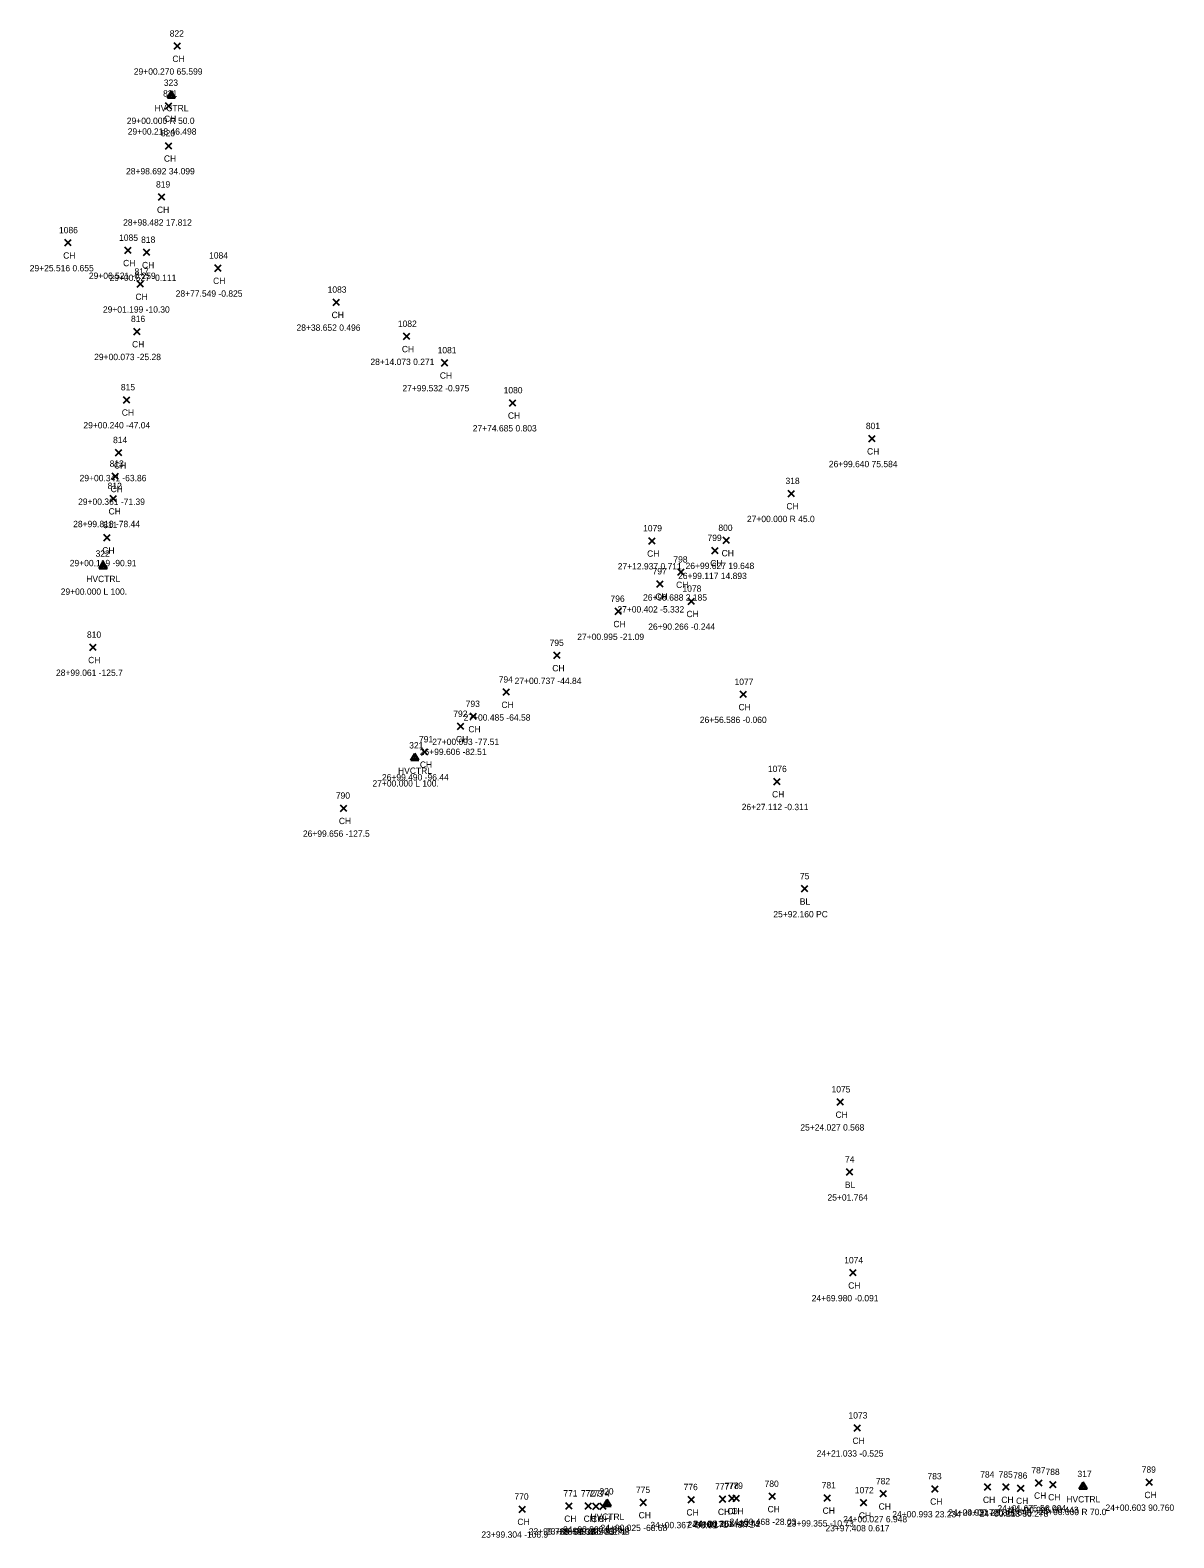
# Model space of a CAD drawing. Extents: x 89316 to 92454, y 84175 to 86051.
# Drawn here: x 90007.9 to 90368.2, y 85575.8 to 86051 of the extents above; entities that cross this region are included whole.
import ezdxf

# ---------------------------------------------------------------- set-up
doc = ezdxf.new("R2010")
doc.units = 0
for name, color, linetype in [('C_A', 7, 'Continuous'), ('C_C', 7, 'Continuous'), ('C_I', 7, 'Continuous'), ('C_TIC', 7, 'Continuous'), ('CPSM', 7, 'Continuous'), ('L_A', 7, 'Continuous'), ('L_C', 7, 'Continuous'), ('L_I', 7, 'Continuous'), ('L_TIC', 7, 'Continuous')]:
    doc.layers.add(name, color=color, linetype=linetype)

msp = doc.modelspace()

# ---------------------------------------------------------------- linework, layer by layer
at = {"layer": 'C_TIC'}
for points in [[(90250.87, 85779.38), (90252.87, 85781.38)], [(90252.87, 85779.38), (90250.87, 85781.38)], [(90265.06, 85690.1), (90267.06, 85692.1)], [(90267.06, 85690.1), (90265.06, 85692.1)]]:
    msp.add_lwpolyline(points, dxfattribs=at)
at = {"layer": 'CPSM'}
for p, q in [((90051.14, 86029.75), (90052.39, 86031.91)), ((90053.64, 86029.75), (90052.39, 86031.91)), ((90052.39, 86030.47), (90052.39, 86031.91)), ((90051.14, 86029.75), (90052.39, 86030.47)), ((90051.14, 86029.75), (90053.64, 86029.75)), ((90052.39, 86030.47), (90052.39, 86030.47)), ((90052.39, 86030.47), (90053.64, 86029.75)), ((90029.64, 85881.33), (90030.89, 85883.5)), ((90029.64, 85881.33), (90030.89, 85882.05)), ((90029.64, 85881.33), (90032.14, 85881.33)), ((90032.14, 85881.33), (90030.89, 85883.5)), ((90030.89, 85882.05), (90030.89, 85883.5)), ((90030.89, 85882.05), (90030.89, 85882.05)), ((90030.89, 85882.05), (90032.14, 85881.33)), ((90127.85, 85820.89), (90129.1, 85823.05)), ((90130.35, 85820.89), (90129.1, 85823.05)), ((90129.1, 85821.61), (90129.1, 85823.05)), ((90127.85, 85820.89), (90129.1, 85821.61)), ((90127.85, 85820.89), (90130.35, 85820.89)), ((90129.1, 85821.61), (90129.1, 85821.61)), ((90129.1, 85821.61), (90130.35, 85820.89)), ((90338.38, 85591.24), (90339.63, 85593.4)), ((90338.38, 85591.24), (90339.63, 85591.96)), ((90338.38, 85591.24), (90340.88, 85591.24)), ((90340.88, 85591.24), (90339.63, 85593.4)), ((90339.63, 85591.96), (90339.63, 85593.4)), ((90339.63, 85591.96), (90339.63, 85591.96)), ((90339.63, 85591.96), (90340.88, 85591.24)), ((90188.44, 85585.74), (90189.69, 85587.91)), ((90188.44, 85585.74), (90189.69, 85586.46)), ((90188.44, 85585.74), (90190.94, 85585.74)), ((90190.94, 85585.74), (90189.69, 85587.91)), ((90189.69, 85586.46), (90189.69, 85587.91)), ((90189.69, 85586.46), (90189.69, 85586.46)), ((90189.69, 85586.46), (90190.94, 85585.74))]:
    msp.add_line(p, q, dxfattribs=at)
at = {"layer": 'L_TIC'}
for points in [[(90053.23, 86045), (90055.23, 86047)], [(90055.23, 86045), (90053.23, 86047)], [(90050.59, 86026.09), (90052.59, 86028.09)], [(90052.59, 86026.09), (90050.59, 86028.09)], [(90050.55, 86013.56), (90052.55, 86015.56)], [(90052.55, 86013.56), (90050.55, 86015.56)], [(90048.36, 85997.42), (90050.36, 85999.42)], [(90050.36, 85997.42), (90048.36, 85999.42)], [(90018.83, 85983.01), (90020.83, 85985.01)], [(90020.83, 85983.01), (90018.83, 85985.01)], [(90037.71, 85980.62), (90039.71, 85982.62)], [(90039.71, 85980.62), (90037.71, 85982.62)], [(90043.66, 85979.99), (90045.66, 85981.99)], [(90045.66, 85979.99), (90043.66, 85981.99)], [(90066.05, 85975.01), (90068.05, 85977.01)], [(90068.05, 85975.01), (90066.05, 85977.01)], [(90041.59, 85969.99), (90043.59, 85971.99)], [(90043.59, 85969.99), (90041.59, 85971.99)], [(90103.39, 85964.26), (90105.39, 85966.26)], [(90105.39, 85964.26), (90103.39, 85966.26)], [(90040.53, 85955.02), (90042.53, 85957.02)], [(90042.53, 85955.02), (90040.53, 85957.02)], [(90125.52, 85953.5), (90127.52, 85955.5)], [(90127.52, 85953.5), (90125.52, 85955.5)], [(90137.48, 85945.17), (90139.48, 85947.17)], [(90139.48, 85945.17), (90137.48, 85947.17)], [(90037.29, 85933.5), (90039.29, 85935.5)], [(90039.29, 85933.5), (90037.29, 85935.5)], [(90158.93, 85932.54), (90160.93, 85934.54)], [(90160.93, 85932.54), (90158.93, 85934.54)], [(90272.06, 85921.27), (90274.06, 85923.27)], [(90274.06, 85921.27), (90272.06, 85923.27)], [(90034.83, 85916.85), (90036.83, 85918.85)], [(90036.83, 85916.85), (90034.83, 85918.85)], [(90033.75, 85909.4), (90035.75, 85911.4)], [(90035.75, 85909.4), (90033.75, 85911.4)], [(90033.12, 85902.37), (90035.12, 85904.37)], [(90035.12, 85902.37), (90033.12, 85904.37)], [(90246.66, 85903.96), (90248.66, 85905.96)], [(90248.66, 85903.96), (90246.66, 85905.96)], [(90031.14, 85890.06), (90033.14, 85892.06)], [(90033.14, 85890.06), (90031.14, 85892.06)], [(90202.78, 85889.04), (90204.78, 85891.04)], [(90204.78, 85889.04), (90202.78, 85891.04)], [(90226.25, 85889.18), (90228.25, 85891.18)], [(90228.25, 85889.18), (90226.25, 85891.18)], [(90222.66, 85886.01), (90224.66, 85888.01)], [(90224.66, 85886.01), (90222.66, 85888.01)], [(90211.91, 85879.21), (90213.91, 85881.21)], [(90213.91, 85879.21), (90211.91, 85881.21)], [(90205.35, 85875.47), (90207.35, 85877.47)], [(90207.35, 85875.47), (90205.35, 85877.47)], [(90215.17, 85870.01), (90217.17, 85872.01)], [(90217.17, 85870.01), (90215.17, 85872.01)], [(90192.15, 85866.83), (90194.15, 85868.83)], [(90194.15, 85866.83), (90192.15, 85868.83)], [(90026.69, 85855.49), (90028.69, 85857.49)], [(90028.69, 85855.49), (90026.69, 85857.49)], [(90172.9, 85852.93), (90174.9, 85854.93)], [(90174.9, 85852.93), (90172.9, 85854.93)], [(90156.88, 85841.38), (90158.88, 85843.38)], [(90158.88, 85841.38), (90156.88, 85843.38)], [(90231.57, 85840.65), (90233.57, 85842.65)], [(90233.57, 85840.65), (90231.57, 85842.65)], [(90142.57, 85830.57), (90144.57, 85832.57)], [(90144.57, 85830.57), (90142.57, 85832.57)], [(90146.47, 85833.71), (90148.47, 85835.71)], [(90148.47, 85833.71), (90146.47, 85835.71)], [(90131.2, 85822.52), (90133.2, 85824.52)], [(90133.2, 85822.52), (90131.2, 85824.52)], [(90242.13, 85813.17), (90244.13, 85815.17)], [(90244.13, 85813.17), (90242.13, 85815.17)], [(90105.67, 85804.77), (90107.67, 85806.77)], [(90107.67, 85804.77), (90105.67, 85806.77)], [(90262.13, 85712.18), (90264.13, 85714.18)], [(90264.13, 85712.18), (90262.13, 85714.18)], [(90266.13, 85658.34), (90268.13, 85660.34)], [(90268.13, 85658.34), (90266.13, 85660.34)], [(90267.47, 85609.41), (90269.47, 85611.41)], [(90269.47, 85609.41), (90267.47, 85611.41)], [(90324.66, 85592.11), (90326.66, 85594.11)], [(90326.66, 85592.11), (90324.66, 85594.11)], [(90359.44, 85592.31), (90361.44, 85594.31)], [(90361.44, 85592.31), (90359.44, 85594.31)], [(90240.72, 85587.86), (90242.72, 85589.86)], [(90242.72, 85587.86), (90240.72, 85589.86)], [(90258.06, 85587.37), (90260.06, 85589.37)], [(90260.06, 85587.37), (90258.06, 85589.37)], [(90275.7, 85588.69), (90277.7, 85590.69)], [(90277.7, 85588.69), (90275.7, 85590.69)], [(90291.94, 85590.24), (90293.94, 85592.24)], [(90293.94, 85590.24), (90291.94, 85592.24)], [(90308.56, 85590.79), (90310.56, 85592.79)], [(90310.56, 85590.79), (90308.56, 85592.79)], [(90314.35, 85590.78), (90316.35, 85592.78)], [(90316.35, 85590.78), (90314.35, 85592.78)], [(90318.99, 85590.45), (90320.99, 85592.45)], [(90320.99, 85590.45), (90318.99, 85592.45)], [(90329.12, 85591.6), (90331.12, 85593.6)], [(90331.12, 85591.6), (90329.12, 85593.6)], [(90161.92, 85583.83), (90163.92, 85585.83)], [(90163.92, 85583.83), (90161.92, 85585.83)], [(90176.68, 85584.83), (90178.68, 85586.83)], [(90178.68, 85584.83), (90176.68, 85586.83)], [(90182.78, 85584.83), (90184.78, 85586.83)], [(90184.78, 85584.83), (90182.78, 85586.83)], [(90185.12, 85584.75), (90187.12, 85586.75)], [(90187.12, 85584.75), (90185.12, 85586.75)], [(90187.35, 85584.77), (90189.35, 85586.77)], [(90189.35, 85584.77), (90187.35, 85586.77)], [(90200.11, 85585.94), (90202.11, 85587.94)], [(90202.11, 85585.94), (90200.11, 85587.94)], [(90215.17, 85586.83), (90217.17, 85588.83)], [(90217.17, 85586.83), (90215.17, 85588.83)], [(90225.07, 85586.99), (90227.07, 85588.99)], [(90227.07, 85586.99), (90225.07, 85588.99)], [(90228.03, 85587.23), (90230.03, 85589.23)], [(90230.03, 85587.23), (90228.03, 85589.23)], [(90229.35, 85587.24), (90231.35, 85589.24)], [(90231.35, 85587.24), (90229.35, 85589.24)], [(90269.47, 85585.84), (90271.47, 85587.84)], [(90271.47, 85585.84), (90269.47, 85587.84)]]:
    msp.add_lwpolyline(points, dxfattribs=at)

# ---------------------------------------------------------------- texts
at = {"layer": 'C_A'}
for s, p in [('HVCTRL', (90047.09, 86025.47)), ('HVCTRL', (90025.59, 85877.05)), ('HVCTRL', (90123.8, 85816.61)), ('BL', (90250.36, 85775.38)), ('BL', (90264.55, 85686.1)), ('HVCTRL', (90334.32, 85586.96)), ('HVCTRL', (90184.38, 85581.46))]:
    msp.add_text(s, height=2, dxfattribs=at).set_placement(p)
at = {"layer": 'C_C'}
for s, p in [('29+00.000 R 50.0', (90038.37, 86021.47)), ('29+00.000 L 100.', (90017.54, 85873.05)), ('27+00.000 L 100.', (90115.75, 85812.61)), ('25+92.160 PC', (90242.02, 85771.38)), ('25+01.764', (90259.08, 85682.1)), ('24+00.000 R 70.0', (90325.61, 85582.96)), ('24+00.000 L 80.0', (90175.76, 85577.46))]:
    msp.add_text(s, height=2, dxfattribs=at).set_placement(p)
at = {"layer": 'C_I'}
for s, p in [('323', (90050.03, 86033.47)), ('322', (90028.53, 85885.05)), ('321', (90127.31, 85824.61)), ('75', (90250.4, 85783.38)), ('74', (90264.6, 85694.1)), ('317', (90337.83, 85594.96)), ('320', (90187.24, 85589.46))]:
    msp.add_text(s, height=2, dxfattribs=at).set_placement(p)
at = {"layer": 'L_A'}
for p in [(90052.72, 86041), (90050.08, 86022.09), (90050.04, 86009.56), (90047.85, 85993.42), (90018.32, 85979.01), (90037.19, 85976.62), (90043.15, 85975.99), (90065.54, 85971.01), (90041.08, 85965.99), (90102.88, 85960.26), (90040.01, 85951.02), (90125.01, 85949.5), (90136.96, 85941.17), (90036.78, 85929.5), (90158.41, 85928.54), (90271.54, 85917.27), (90034.32, 85912.85), (90033.24, 85905.4), (90032.61, 85898.37), (90246.14, 85899.96), (90030.63, 85886.06), (90202.27, 85885.04), (90222.15, 85882.01), (90225.73, 85885.18), (90211.39, 85875.21), (90204.84, 85871.47), (90214.66, 85866.01), (90191.64, 85862.83), (90026.18, 85851.49), (90172.39, 85848.93), (90156.37, 85837.38), (90231.06, 85836.65), (90145.96, 85829.71), (90142.05, 85826.57), (90130.68, 85818.52), (90241.62, 85809.17), (90105.16, 85800.77), (90261.62, 85708.18), (90265.61, 85654.34), (90266.96, 85605.41), (90324.15, 85588.11), (90328.61, 85587.6), (90358.92, 85588.31), (90214.65, 85582.83), (90224.56, 85582.99), (90227.52, 85583.23), (90228.84, 85583.24), (90240.21, 85583.86), (90257.55, 85583.37), (90275.19, 85584.69), (90291.43, 85586.24), (90308.05, 85586.79), (90313.84, 85586.78), (90318.48, 85586.45), (90161.4, 85579.83), (90176.16, 85580.83), (90182.27, 85580.83), (90184.61, 85580.75), (90186.84, 85580.77), (90199.6, 85581.94), (90268.96, 85581.84)]:
    msp.add_text('CH', height=2, dxfattribs=at).set_placement(p)
at = {"layer": 'L_C'}
for s, p in [('29+00.270 65.599', (90040.57, 86037)), ('29+00.218 46.498', (90038.66, 86018.09)), ('28+98.692 34.099', (90038.12, 86005.56)), ('28+98.482 17.812', (90037.2, 85989.42)), ('29+25.516 0.655', (90007.78, 85975.01)), ('29+06.521 -0.259', (90026.41, 85972.62)), ('29+00.527 -0.111', (90032.92, 85971.99)), ('28+77.549 -0.825', (90053.76, 85967.01)), ('29+01.199 -10.30', (90030.84, 85961.99)), ('28+38.652 0.496', (90091.82, 85956.26)), ('29+00.073 -25.28', (90028.08, 85947.02)), ('28+14.073 0.271', (90115.1, 85945.5)), ('27+99.532 -0.975', (90125.18, 85937.17)), ('29+00.240 -47.04', (90024.68, 85925.5)), ('27+74.685 0.803', (90147.33, 85924.54)), ('26+99.640 75.584', (90259.51, 85913.27)), ('29+00.341 -63.86', (90023.49, 85908.85)), ('29+00.361 -71.39', (90023.02, 85901.4)), ('28+99.818 -78.44', (90021.47, 85894.37)), ('27+00.000 R 45.0', (90233.71, 85895.96)), ('29+00.119 -90.91', (90020.39, 85882.06)), ('27+12.937 0.711', (90193.01, 85881.04)), ('26+99.117 14.893', (90212.02, 85878.01)), ('26+99.627 19.648', (90214.38, 85881.18)), ('26+99.688 2.185', (90200.98, 85871.21)), ('27+00.402 -5.332', (90192.9, 85867.47)), ('27+00.995 -21.09', (90180.26, 85858.83)), ('26+90.266 -0.244', (90202.61, 85862.01)), ('28+99.061 -125.7', (90016.05, 85847.49)), ('27+00.737 -44.84', (90160.53, 85844.93)), ('27+00.485 -64.58', (90144.47, 85833.38)), ('26+56.586 -0.060', (90218.88, 85832.65)), ('27+00.093 -77.51', (90134.59, 85825.71)), ('26+99.606 -82.51', (90130.65, 85822.57)), ('26+99.490 -96.44', (90118.73, 85814.52)), ('26+27.112 -0.311', (90232.06, 85805.17)), ('26+99.656 -127.5', (90093.83, 85796.77)), ('25+24.027 0.568', (90250.53, 85704.18)), ('24+69.980 -0.091', (90254.12, 85650.34)), ('24+21.033 -0.525', (90255.67, 85601.41)), ('24+00.931 39.860', (90297.11, 85582.79)), ('24+00.720 45.648', (90301.7, 85582.78)), ('24+01.675 56.004', (90312.61, 85584.11)), ('24+00.995 60.443', (90316.55, 85583.6)), ('24+00.603 90.760', (90346.65, 85584.31)), ('24+00.025 -68.68', (90187.57, 85577.94)), ('24+00.367 -53.61', (90203.27, 85578.83)), ('24+00.171 -43.71', (90214.96, 85578.99)), ('24+00.301 -40.74', (90216.63, 85579.23)), ('24+00.268 -39.42', (90216.93, 85579.24)), ('24+00.468 -28.03', (90228.23, 85579.86)), ('23+99.355 -10.73', (90246.33, 85579.37)), ('23+97.408 0.617', (90258.44, 85577.84)), ('24+00.027 6.948', (90264.02, 85580.69)), ('24+00.993 23.234', (90279.49, 85582.24)), ('24+00.213 50.278', (90307.03, 85582.45)), ('23+99.304 -106.9', (90150.06, 85575.83)), ('23+99.765 -92.15', (90164.98, 85576.83)), ('23+99.543 -86.05', (90170.44, 85576.83)), ('23+99.381 -83.71', (90174.61, 85576.75)), ('23+99.325 -81.48', (90175.7, 85576.77))]:
    msp.add_text(s, height=2, dxfattribs=at).set_placement(p)
at = {"layer": 'L_I'}
for s, p in [('822', (90051.87, 86049)), ('821', (90049.79, 86030.09)), ('820', (90049.1, 86017.56)), ('819', (90047.56, 86001.42)), ('1086', (90017, 85987.01)), ('1085', (90035.93, 85984.62)), ('818', (90042.87, 85983.99)), ('1084', (90064.28, 85979.01)), ('817', (90040.8, 85973.99)), ('1083', (90101.62, 85968.26)), ('816', (90039.68, 85959.02)), ('1082', (90123.75, 85957.5)), ('1081', (90136.27, 85949.17)), ('815', (90036.49, 85937.5)), ('1080', (90157.07, 85936.54)), ('801', (90271.18, 85925.27)), ('814', (90034.03, 85920.85)), ('813', (90032.95, 85913.4)), ('812', (90032.32, 85906.37)), ('318', (90245.86, 85907.96)), ('811', (90030.91, 85894.06)), ('1079', (90201, 85893.04)), ('800', (90224.72, 85893.18)), ('799', (90221.29, 85890.01)), ('798', (90210.54, 85883.21)), ('797', (90203.98, 85879.47)), ('1078', (90213.4, 85874.01)), ('796', (90190.73, 85870.83)), ('810', (90025.81, 85859.49)), ('795', (90171.54, 85856.93)), ('794', (90155.52, 85845.38)), ('1077', (90229.8, 85844.65)), ('792', (90141.2, 85834.57)), ('793', (90145.11, 85837.71)), ('791', (90130.4, 85826.52)), ('1076', (90240.3, 85817.17)), ('790', (90104.22, 85808.77)), ('1075', (90260.36, 85716.18)), ('1074', (90264.35, 85662.34)), ('1073', (90265.7, 85613.41)), ('782', (90274.34, 85592.69)), ('783', (90290.58, 85594.24)), ('784', (90307.2, 85594.79)), ('785', (90312.99, 85594.78)), ('786', (90317.58, 85594.45)), ('787', (90323.3, 85596.11)), ('788', (90327.76, 85595.6)), ('789', (90358.07, 85596.31)), ('770', (90160.47, 85587.83)), ('771', (90175.88, 85588.83)), ('772', (90181.42, 85588.83)), ('773', (90183.76, 85588.75)), ('774', (90185.99, 85588.77)), ('775', (90198.75, 85589.94)), ('776', (90213.75, 85590.83)), ('777', (90223.7, 85590.99)), ('778', (90226.67, 85591.23)), ('779', (90227.98, 85591.24)), ('780', (90239.27, 85591.86)), ('781', (90257.26, 85591.37)), ('1072', (90267.7, 85589.84))]:
    msp.add_text(s, height=2, dxfattribs=at).set_placement(p)

doc.saveas('drawing.dxf')
